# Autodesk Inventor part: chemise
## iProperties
Shininess: 21.0
Length Units: 11269
Angle Units: 11279
Time Units: 11290
Mass Units: 11283
Length Display Precision: 3
Angle Display Precision: 2
Compacted: True
Created: 2001-12
Part Number: chemise
Material: Par défaut
Document SubType Name: Modélisation
Designer: pichon
Density: 0.0
Volumn: 0.0
Area: 0.0
PropertySet Name: Model Information
Control State: 0
Master: False
Checked Out: False
Author: pichon
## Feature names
1. Révolution1 [Revolution]
2. Chanfrein1 [Chamfer]
3. Extrusion1
